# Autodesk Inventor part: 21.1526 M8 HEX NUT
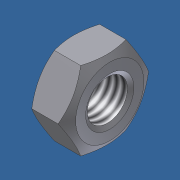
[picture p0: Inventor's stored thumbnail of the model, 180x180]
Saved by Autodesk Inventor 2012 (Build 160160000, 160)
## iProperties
Created: 2006-02
Part Number: 21.1526 M8 HEX NUT
Material: Steel, Mild
Description: M8 HEX NUT
Document SubType Name: Modeling
Standard: DIN 934
Designer: Andy Moles
Standards Organization: DIN
Language: en-US
Size Designation: M8
Categories: <MemberInstance><Categories><Category DisplayName="Fasteners" InternalName="e4da775c-781d-43d5-af7c-5136215cf5a6" Mnemonic="FSTN"><Category DisplayName="Nuts" I
Mass: 5.38751 g
Surface Area: 5.92403 cm^2
Volume: 0.685433 cm^3
Density: 7.86 g/cm^3
Author: Andy Moles
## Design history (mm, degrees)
body "Solid1"
workaxis "Work Axis1"
workplane "Work Plane1"
sketch "Sketch1"
  geometry: L1 (-7.506, 0)-(-3.753, 6.5); L2 (-3.753, 6.5)-(3.753, 6.5); L3 (3.753, 6.5)-(7.506, 0); L4 (7.506, 0)-(3.753, -6.5); L5 (3.753, -6.5)-(-3.753, -6.5); L6 (-3.753, -6.5)-(-7.506, 0); 2 further points
  constraints: 12 end point, 1 coincident, 1 horizontal, 11 other
  dimensions: "d0" = 15.01111 distance of L3.end L1.start (= 1.1547 x SW)
extrude "Body" new body sketch "Sketch1" distance "d1" = 6.5 (= KOH); taper "d2" = 0 deg
revolve "Chamfer1" stored, may be unused: angle "d7" = 90 deg
sketch "Sketch3"
  geometry: 4 further points
  constraints: 1 coincident, 1 other
hole "Thread" sketch "Sketch3" diameter "d25" = 6.647; stored, may be unused: countersink angle "d29" = 82 deg, drill point angle "d31" = 118 deg; dims "d26" = 6, "d27" = 4, "d28" = 2, "d30" = 8
chamfer "Chamfer2" distance "d8" = 0.67658 (= -0.5 x GD1 + 0.5 x NND); stored, may be unused: angle "d9" = 30 deg, second distance "d40" = 0.67658 (= -0.5 x GD1 + 0.5 x NND)
chamfer "Chamfer3" distance "d10" = 0.67658 (= -0.5 x GD1 + 0.5 x NND); stored, may be unused: angle "d11" = 30 deg, second distance "d41" = 0.67658 (= -0.5 x GD1 + 0.5 x NND)
sketch "Sketch2"
  geometry: L1 (0, 3.753)-(0, 7.506) reference; L2 (0, 7.506)-(6.5, 7.506) reference; L3 (6.5, 3.753)-(6.5, 7.506) reference; L4 (-0.65, 0)-(8.45, 0) reference; L5 (1.071, 7.506)-(0, 5.65); L6 (5.429, 7.506)-(6.5, 5.65)
  constraints: 4 end point, 4 point on line
  dimensions: "d3" = 30 deg angle of L1 L5 (= ANG1); "d4" = 30 deg angle of L3 L6 (= ANG2); "d5" = 11.3 diameter of L5.end L4 (= SW0); "d6" = 11.3 diameter of L6.end L4 (= SW01)
other parameters: "ANG1" = 30 deg [user parameter; used in 1 equation term], "ANG2" = 30 deg [user parameter; used in 1 equation term], "NND" = 8 [user parameter; used in 4 equation terms], "KOH" = 6.5 [user parameter; used in 1 equation term], "SW" = 13 [user parameter; used in 2 equation terms], "SW0" = 11.3 (= SW01) [user parameter; used in 1 equation term], "SW01" = 11.3 [user parameter; used in 2 equation terms], "GD1" = 6.64684 (computed from THREADDIA, PTC, TOA) [user parameter; used in 4 equation terms], "d13" = 0, "d14" = 0, "d39" = 0, "d42" = 0, "GUL" = 0.67658 (= 0.541266 x PTC) [user parameter], "TPU" = 8 (computed from PTC) [user parameter], "THREADDIA" = 8 [user parameter; used in 1 equation term], "TOA" = 30 deg [user parameter; used in 1 equation term], "PTC" = 1.25 [user parameter; used in 4 equation terms], "E0" = 15.015 (= 1.155 x SW) [user parameter], "GAL" = 0.67658 (= 0.541266 x PTC) [user parameter]
